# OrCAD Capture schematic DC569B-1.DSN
size A; title: Li-Ion Battery Charger; rev: 1; note: DEMO CIRCUIT 569B
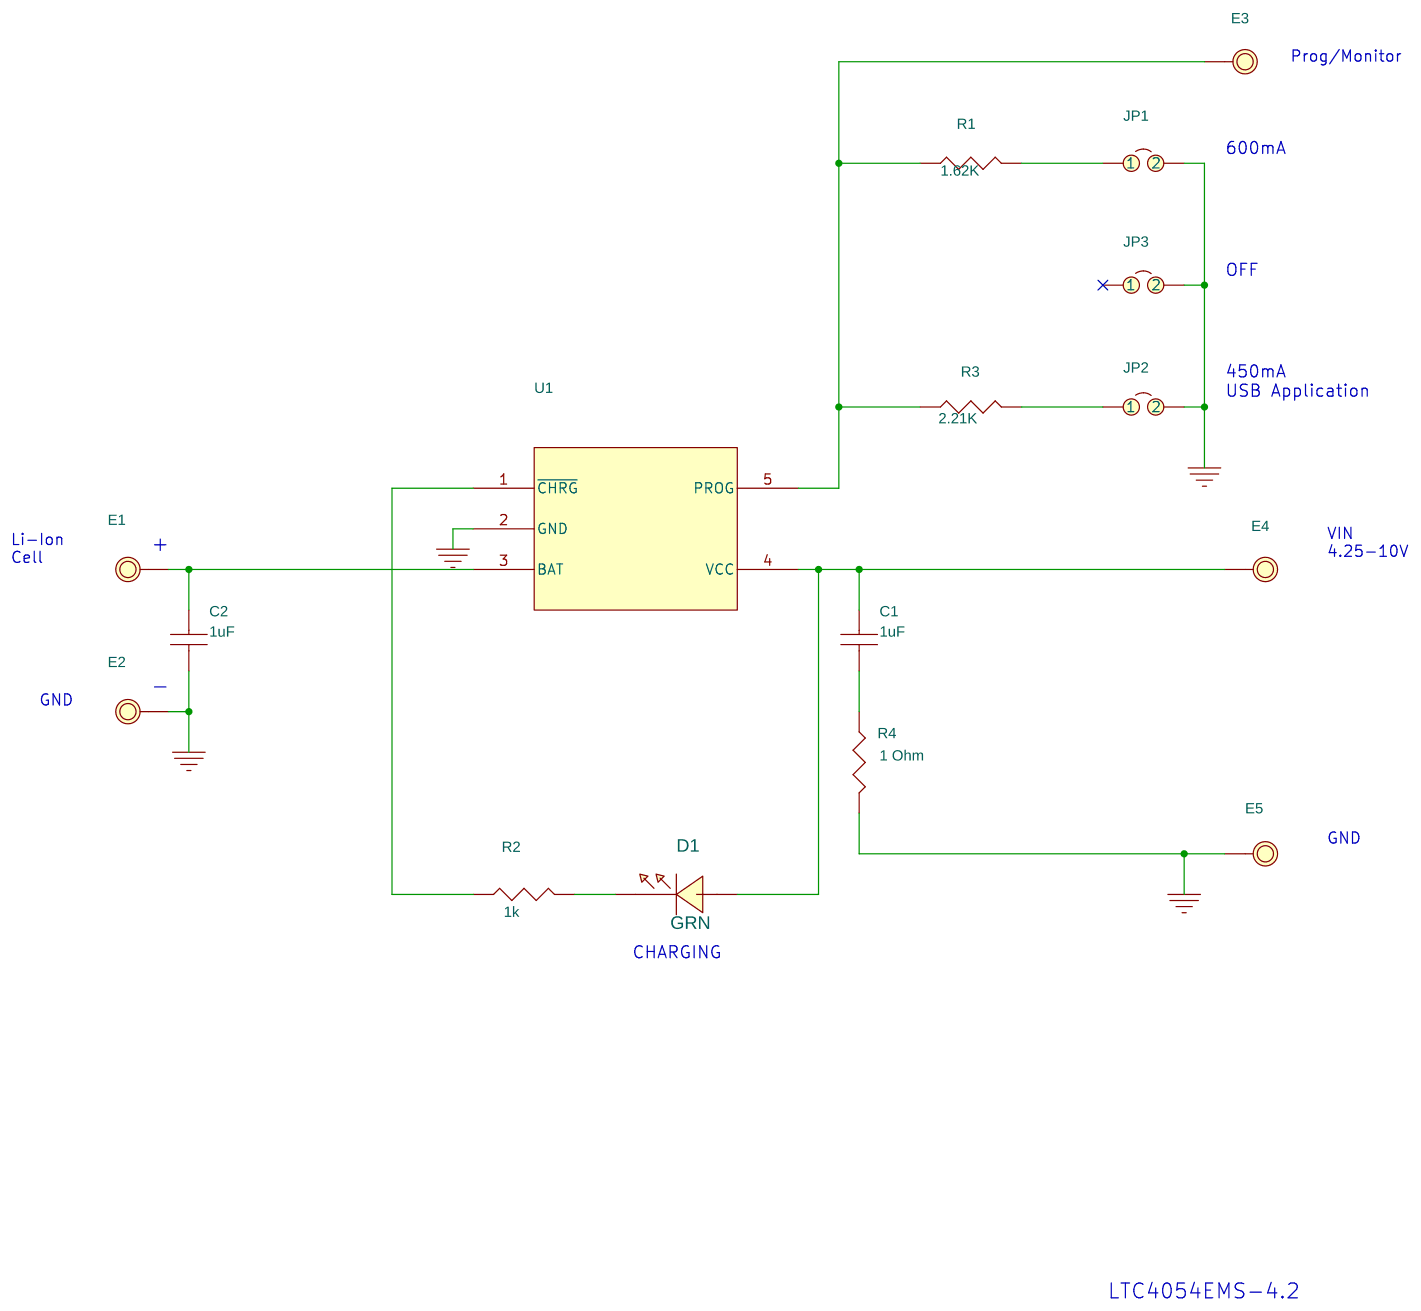
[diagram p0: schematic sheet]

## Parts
C1  1uF  [0603]
C2  1uF  [0603]
D1  GRN  [LED-WURTH-150060GS75000]
E1  Testpoint  [MILLMAX-2501-2]
E2  Testpoint  [MILLMAX-2501-2]
E3  Testpoint  [MILLMAX-2501-2]
E4  Testpoint  [MILLMAX-2501-2]
E5  Testpoint  [MILLMAX-2501-2]
JP1  2pins 2mm Ctrs.  [CommCon2802s02g2]
JP2  2pins 2mm Ctrs.  [CommCon2802s02g2]
JP3  2pins 2mm Ctrs.  [CommCon2802s02g2]
R1  1.62K  [0402]
R2  1k  [0402]
R3  2.21K  [0402]
R4  1 Ohm  [0402]
U1  DC/DC Converter  [SOT23-s5]

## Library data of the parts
C1 C2 = LMK107BJ105MA
D1 = ln1351-c-tr_1: 5th Part Field: 150060GS75000; 9th Part Field: CHGR
E1-E5 = MillMax-2501-2
JP1 = Commcon2802s02g2_2
JP2 = Commcon2802s02g2
JP3 = Commcon2802s02g2_1
R1 = CR05-1621FM
R2 = CR05-331JM: 5th Part Field: CR05-102JM
R3 = CR05-2211FM
R4 = CR05-1R0JM
U1 = LTC4054ES5-4.2

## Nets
gnd: C2.2 E2.1 E5.1 JP1.2 JP2.2 JP3.2 R4.2 U1.2(GND)
N832549: C1.1 D1.2(A) E4.1 U1.4(VCC)
N854617: R2.1 U1.1(~{CHRG})
N855122: C2.1 E1.1 U1.3(BAT)
N856588: E3.1 R1.1 R3.1 U1.5(PROG)
N857896: JP1.1 R1.2
N857946: JP2.1 R3.2
N859789: D1.1(K) R2.2
N860819: C1.2 R4.1

Not connected (* = marked no-connect by the designer): JP3 1*

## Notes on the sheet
- Prog/Monitor
- 600mA
- OFF
- 450mA
  USB Application
- Li-Ion
  Cell
- +
- VIN
  4.25-10V
- -
- GND
- GND
- CHARGING
- LTC4054EMS-4.2
